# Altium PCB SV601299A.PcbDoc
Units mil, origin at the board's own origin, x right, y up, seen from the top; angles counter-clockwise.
Board outline 3580 x 5000 mil, 2 copper layers (Top Layer, Bottom Layer), stack 62 mil thick; 30 components, 7 nets, 89 pads, 15 vias.
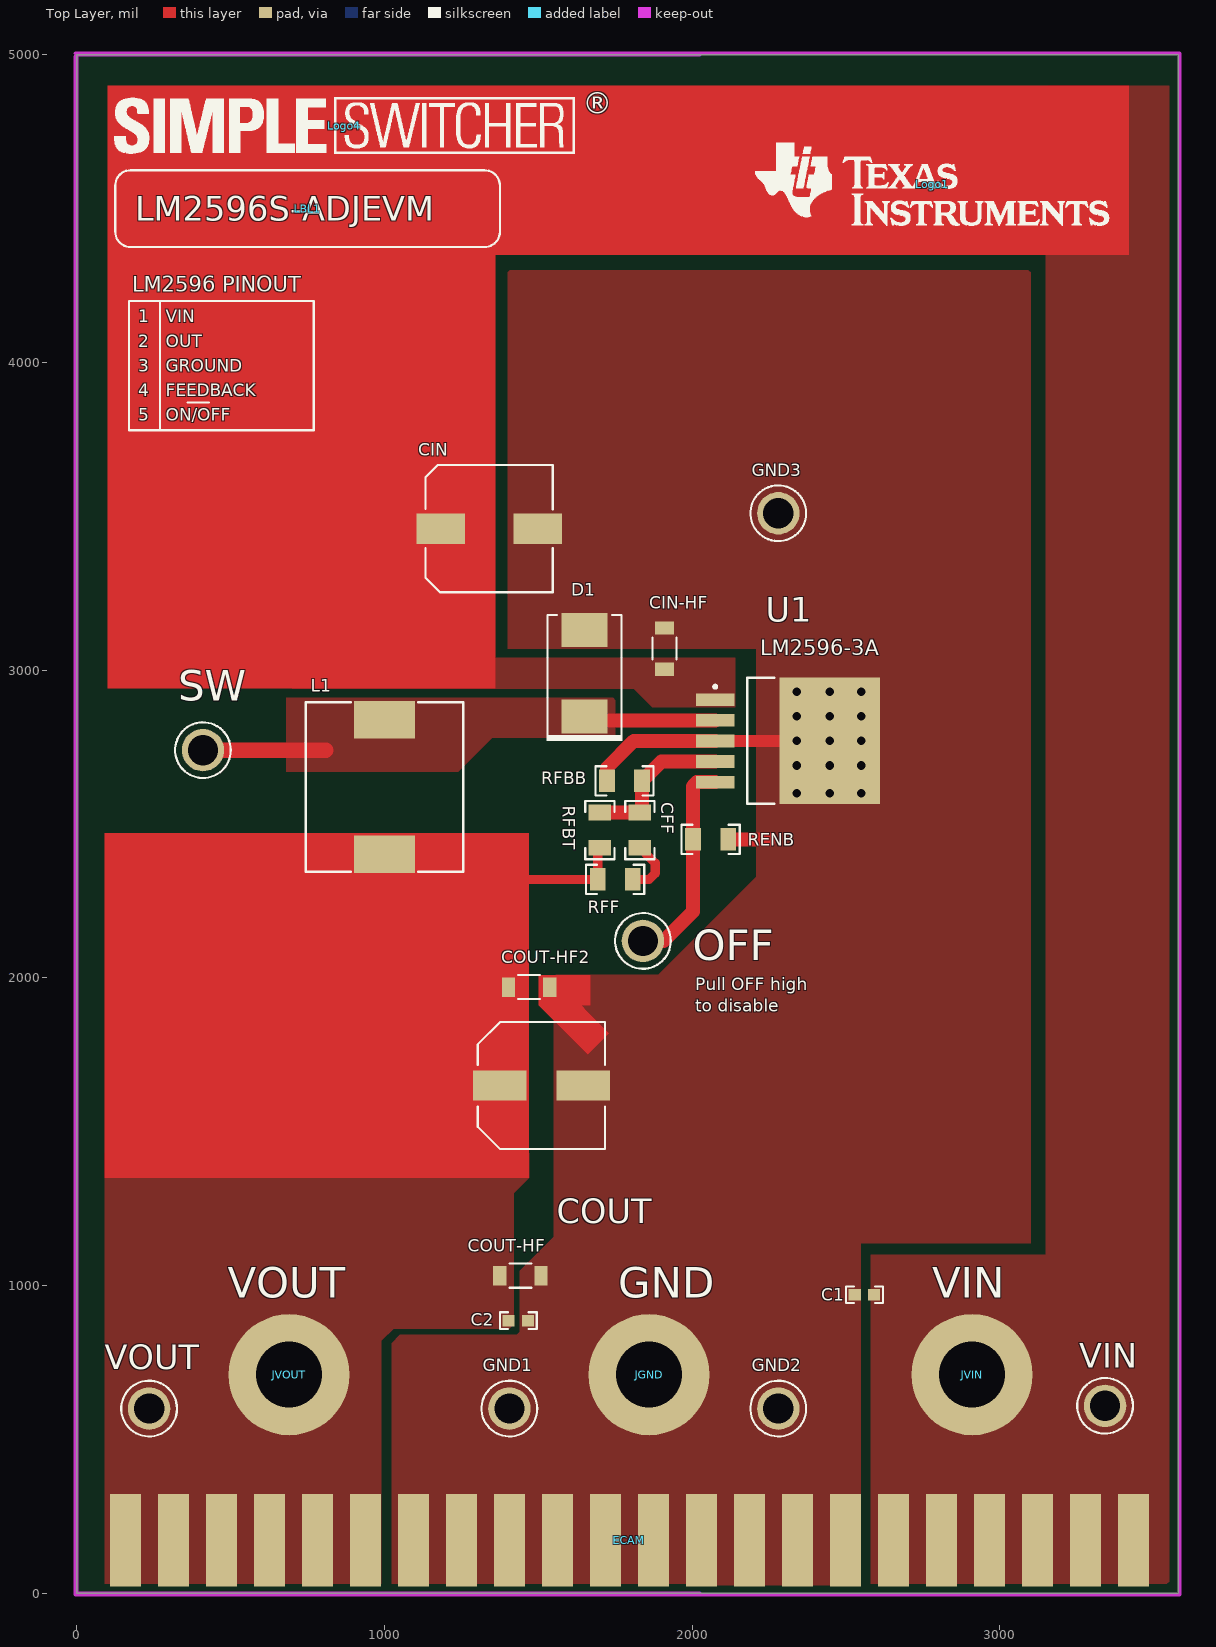
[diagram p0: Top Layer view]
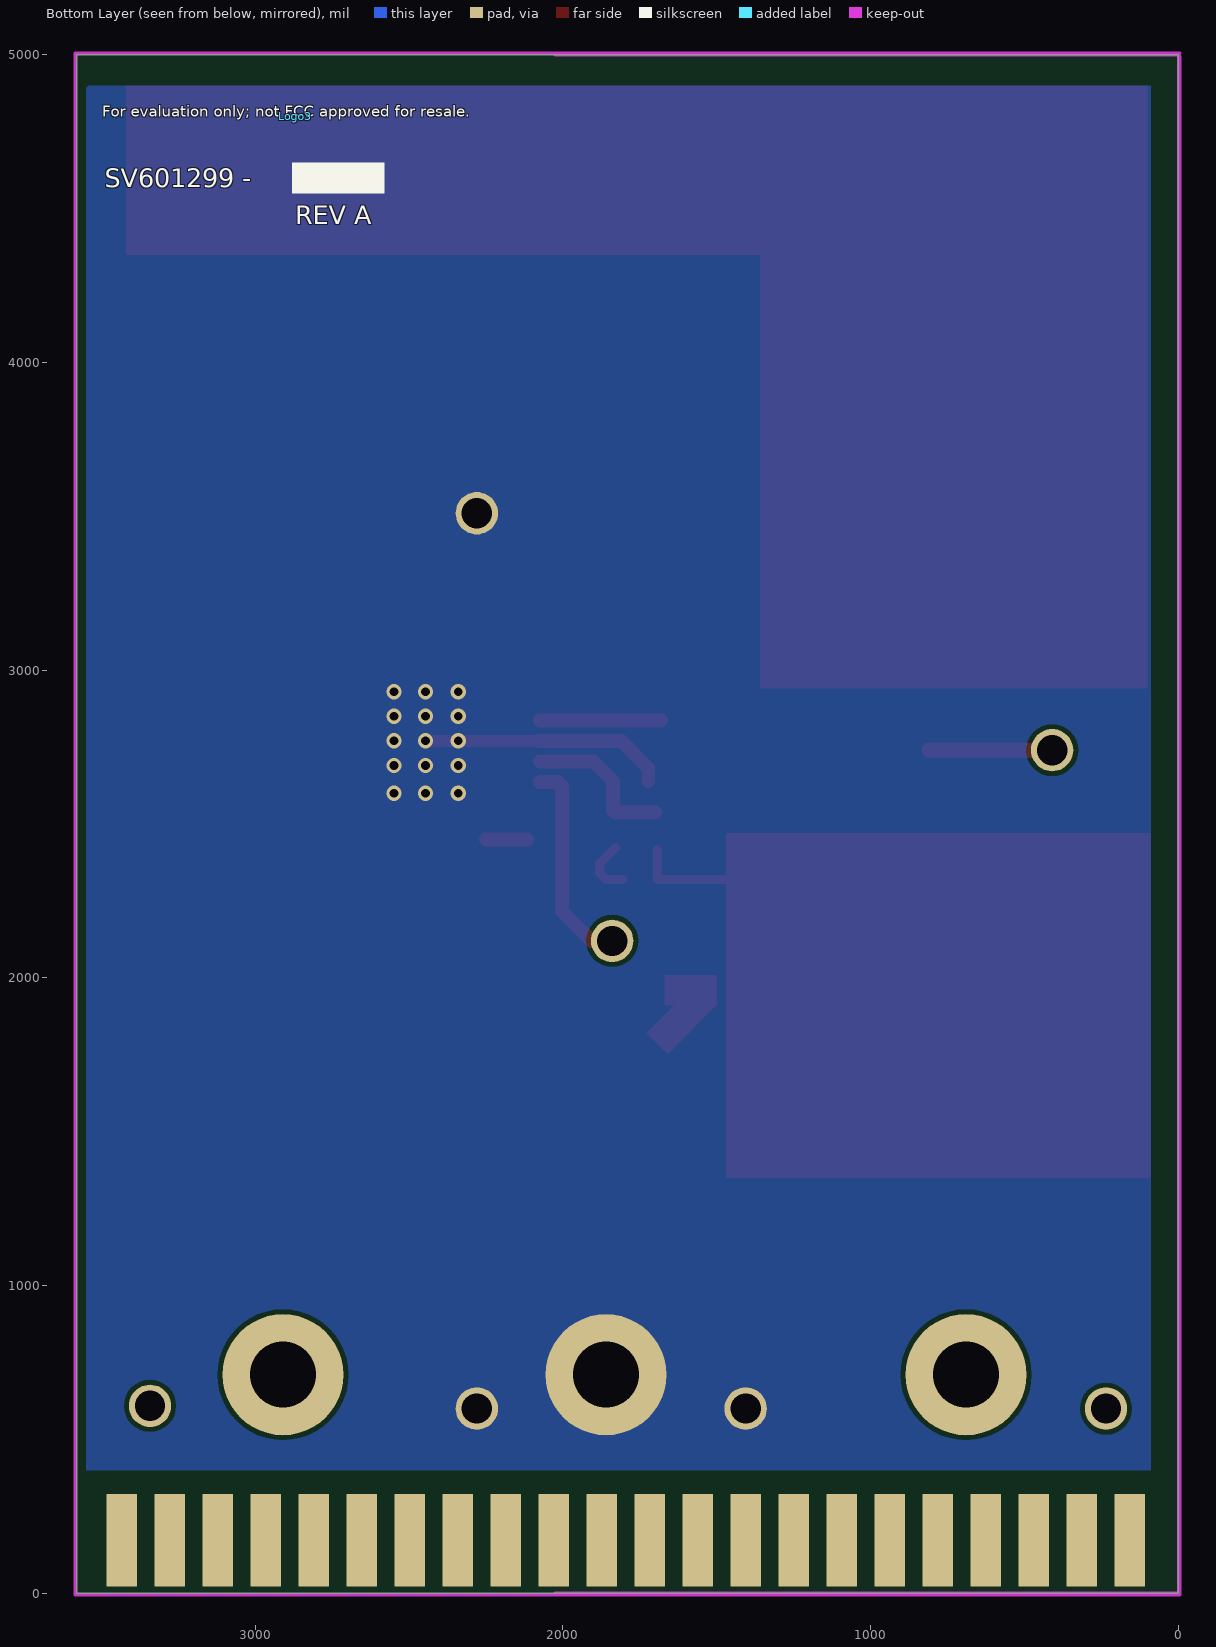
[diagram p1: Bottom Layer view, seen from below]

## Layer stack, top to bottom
Top Solder: solder mask 0.4, Solder Resist, Dk 3.5
Top Layer: signal copper 1.4
Dielectric1: core 59.2, FR-4, Dk 4.8
Bottom Layer: signal copper 1.4
Bottom Solder: solder mask 0.4, Solder Resist, Dk 3.5

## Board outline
0,0 0,5000 3580,5000 3580,0

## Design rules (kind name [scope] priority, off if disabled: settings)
AcuteAngle [All] p1: minimum=4.50000000000000E+0001 checktracksonly=FALSE
AssemblyTestPointUsage [All] p1: valid=2
Clearance Clearance_Keepouts [((IsTrack Or IsArc) And Not InPoly) And IsFree and IsKeepOut vs ((IsTrack Or IsArc) And Not InPoly) And IsFree and IsKeepOut] p1: gap=0
Clearance Clearance_BoardEdge_MountingHoles [OnCopper and InComponentClass('Mounting Holes') vs IsKeepOut] p2: gap=40
Clearance Clearance_BoardEdge_Poly [OnCopper and InPoly vs IsKeepOut] p3: gap=25
Clearance Clearance_BoardEdge [OnCopper and Not InComponentClass('Logo') and not InComponentClass('FiducialMark') and not InRegion(1000,500,4000,800) and Not IsKeepout vs IsKeepOut] p4: gap=15
Clearance Clearance_Poly [InPolygon] p5: gap=15
Clearance [All] p6: gap=7.87
ComponentClearance ComponentClearance_MountingHoles_FiducialMarks [InComponentClass('Mounting Holes') vs InComponentClass('FiducialMark')] p1: gap=50 collisioncheckmode=3 verticalgap=10 showdistances=FALSE
ComponentClearance ComponentClearance_Shunt [InComponentClass('Header') vs InComponentClass('Shunt')] p2: gap=0 collisioncheckmode=3 verticalgap=0 showdistances=FALSE
ComponentClearance ComponentClearance_Logo [InComponentClass('Logo')] p3: gap=50 collisioncheckmode=3 verticalgap=10 showdistances=FALSE
ComponentClearance ComponentClearance_ScrewToNut [(HasFootprint('NY PMS 440 0025 PH')) vs (HasFootprint('Keystone_1902C'))] p4: gap=5 collisioncheckmode=3 verticalgap=10 showdistances=FALSE
ComponentClearance ComponentClearance_MountingHoles [InComponentClass('Mounting Holes')] p5: gap=250 collisioncheckmode=3 verticalgap=100000 showdistances=FALSE
ComponentClearance ComponentClearance_SmallPassives [HasFootprint('0201*') or HasFootprint('0402*') or HasFootprint('0508') or HasFootprint('0603*') or HasFootprint('0612') or HasFootprint('0805*') or HasFootprint('0815*') or HasFootprint('0830*') or HasFootprint('1206*') or HasFootprint('1210*') or HasFootprint('1808*') or HasFootprint('1812*') or HasFootprint('1825*') or HasFootprint('2010*') or HasFootprint('2220*') or HasFootprint('2225*') or HasFootprint('2512*') or HasFootprint('2728*') or HasFootprint('3518*') vs HasFootprint('0201*') or HasFootprint('0402*') or HasFootprint('0508') or HasFootprint('0603*') or HasFootprint('0612') or HasFootprint('0805*') or HasFootprint('0815*') or HasFootprint('0830*') or HasFootprint('1206*') or HasFootprint('1210*') or HasFootprint('1808*') or HasFootprint('1812*') or HasFootprint('1825*') or HasFootprint('2010*') or HasFootprint('2220*') or HasFootprint('2225*') or HasFootprint('2512*') or HasFootprint('2728*') or HasFootprint('3518*')] p6: gap=20 collisioncheckmode=3 verticalgap=10 showdistances=FALSE
ComponentClearance ComponentClearance_THtoSMT [IsThruComponent vs IsSMTComponent] p7: gap=100 collisioncheckmode=3 verticalgap=30 showdistances=FALSE
ComponentClearance ComponentClearance_THtoTH [IsThruComponent vs IsThruComponent] p8: gap=118.11 collisioncheckmode=3 verticalgap=30 showdistances=FALSE
ComponentClearance [All] p9: gap=40 collisioncheckmode=3 verticalgap=10 showdistances=FALSE
DiffPairsRouting [All] p1: maxlimit=100 minlimit=10 mostfreqgap=10 toplayer_minwidth=15 toplayer_maxwidth=15 toplayer_prefwidth=15 bottomlayer_minwidth=15 bottomlayer_maxwidth=15 bottomlayer_prefwidth=15 maxuncoupledlength=1000
FabricationTestPointUsage TestPointUsage [All] p1: valid=2 allowmultiple=FALSE
FabricationTestpoint Testpoint [All] p1: side=3 testpointundercomponent=TRUE minsize=40 maxsize=100 preferedsize=60 minholesize=0 maxholesize=40 preferedholesize=32 testpointgrid=1 allowsidetop=TRUE allowsidebottom=TRUE usegrid=TRUE gridtolerance=0.01
FanoutControl Fanout_LCC [IsLCC] p1: bgadir=Out bgaviamode=Centered fanoutstyle=Auto fanoutdirection=Alternating viagrid=1 // Fanout_LCC (Default Rule)
FanoutControl Fanout_BGA [IsBGA] p2: bgadir=Out bgaviamode=Centered fanoutstyle=Auto fanoutdirection=Alternating viagrid=1 // Fanout_BGA (Default Rule)
FanoutControl Fanout_Default [All] p4: bgadir=Out bgaviamode=Centered fanoutstyle=Auto fanoutdirection=Alternating viagrid=1 // Fanout_Default (Default Rule)
FanoutControl Fanout_Small [(CompPinCount < 5)] p5: bgadir=Out bgaviamode=Centered fanoutstyle=Auto fanoutdirection=OutThenIn viagrid=1 // Fanout_Small (Default Rule)
HoleSize [All] p1: absolutevalues=TRUE maxlimit=251 minlimit=8 maxpercent=80.000 minpercent=20.000
MinimumAnnularRing MinimumAnnularRing_ThermalPadVias [IsVia and InAnyComponent] p1: minimumring=5.91
MinimumAnnularRing [All] p2: minimumring=6
MinimumSolderMaskSliver MinimumSolderMaskSliver_Logo [InComponentClass('Logo') vs InComponentClass('Logo')] p1: minsoldermaskwidth=0.7
MinimumSolderMaskSliver [All] p2: minsoldermaskwidth=3
PlaneConnect [All] p1: planeconnectstyle=Relief reliefexpansion=10 reliefentries=4 reliefconductorwidth=10 reliefairgap=10
PolygonConnect [All] p1: connectstyle=Direct reliefconductorwidth=10 reliefentries=4 polygonreliefangle="90 Angle" airgapwidth=10
RoutingVias ThermalPadVias [IsVia and InAnyComponent] p1: holewidth=7.87 width=19.68 viastyle="Through Hole" minholewidth=7.87 minwidth=19.68 maxholewidth=12.99 maxwidth=23.62
RoutingVias [All] p2: holewidth=16 width=34 viastyle="Through Hole" minholewidth=7.87 minwidth=24 maxholewidth=40 maxwidth=65
SilkToBoardRegionClearance [Not ((IsComment or IsDesignator) And (Hide <> 'False')) and not InRegion(1000,500,4000,800)] p1:
SilkToSilkClearance SilkToSilkClearance_Pb-FreeLogo [(HasFootprint('Pb-Free_Overlay_Medium') OR HasFootprint('Pb-Free_Overlay_Small')) vs (HasFootprint('Pb-Free_Overlay_Medium') OR HasFootprint('Pb-Free_Overlay_Small'))] p1: silktosilkclearance=0
SilkToSilkClearance [All] p2: silktosilkclearance=4
SilkToSolderMaskClearance "Silk to Solder Mask Opening" [All] p1: minsilkscreentomaskgap=3 clearancetoexposedcopper=FALSE
SolderMaskExpansion [All] p1: expansion=1.97
Width [All] p1: maxlimit=100 minlimit=6 preferedwidth=10 checkconnectedcopper=TRUE
15 further rules are at their usual default settings.

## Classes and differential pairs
component class Label: LBL1
component class Logo: Logo1 Logo4

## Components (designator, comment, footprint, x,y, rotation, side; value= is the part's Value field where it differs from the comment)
C1 "C1608X7R2A223K080AA" 0603 2560,970 r180 top
C2 "C1608X7R1C224K080AC" 0603 1435,886 r0 top
CFF "12065C332KAT2A" 1206 1830,2480 r270 top
CIN "EEHZC1H101P" SM_RADIAL_10BMM 1340,3460 r0 top
CIN-HF "C3216X7R2A474K160AA" 1206_180 1910,3070 r90 top
COUT "EEE-FP1V331AP" CAPAE1030X1080 1510,1650 r0 top
COUT-HF "C3216X7R2A474K160AA" 1206_180 1442,1032 r0 top
COUT-HF2 "C3216X7R2A474K160AA" 1206_180 1470,1970 r0 top
D1 "B550C-13-F" SMC 1650,2990 r90 top
ECAM "PCB Edge Pattern Feature" "EDAC 2X22_am" 1796,172 r0 top
GND1 "Suggest using a net name here" Keystone1502-2 1406,600 r0 top locked
GND2 "Suggest using a net name here" Keystone1502-2 2280,600 r270 top
GND3 "Suggest using a net name here" Keystone1502-2 2280,3510 r0 top
JGND "575-8" Keystone575-8 1860,710 r90 top
JVIN "575-8" Keystone575-8 2910,710 r90 top
JVOUT "575-8" Keystone575-8 690,710 r90 top
L1 "SRP1265A-470M" SRP1265A 1000,2620 r270 top
LBL1 "Size: 1.25\" x 0.25\"" Label_1250x250 750,4500 r0 top
Logo1 "Texas Instruments" TI_Stacked_Overlay_Medium 2780,4580 r0 top
Logo3 "FCC disclaimer" FCC_disclaimer 2870,4800 r180 bottom
Logo4 "Simple Switcher" SS_Overlay_Medium 870,4770 r0 top
OFF "Suggest using a net name here" Keystone1502-2 1840,2120 r270 top
RENB "CRCW12061K02FKEA" 1206 2060,2450 r180 top
RFBB "ERJ-8ENF1001V" 1206 1780,2640 r0 top
RFBT "CRCW12063K09FKEA" 1206 1700,2480 r270 top
RFF "CRCW1206100RJNEA" 1206 1750,2320 r0 top
SW "Suggest using a net name here" Keystone1502-2 410,2740 r90 top
U1 "LM2596S-ADJ/NOPB" TS5B_N 2311,2770 r0 top
VIN "Suggest using a net name here" Keystone1502-2 3342,609 r0 top
VOUT "Suggest using a net name here" Keystone1502-2 235,600 r0 top locked

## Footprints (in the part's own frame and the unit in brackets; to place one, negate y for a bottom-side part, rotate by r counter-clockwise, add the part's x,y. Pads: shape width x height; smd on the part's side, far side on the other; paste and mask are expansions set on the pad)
0603 [mm] "0603 from SM-752 data"
  rect 1x0.95 smd: 1(-0.8,0) 2(0.8,0)
  silkscreen extent -1.52,-0.69 1.52,0.69, body extent -0.87,-0.47 0.87,0.47, height 1
1206 [mm] "1206 from SM-752 data"
  rect 1.3x1.85 smd: 1(-1.45,0) 2(1.45,0)
  silkscreen extent -2.4,-1.21 2.4,1.21, body extent -1.7,-0.9 1.7,0.9, height 1.35
1206_180 [mm] "1206_180"
  rect 1.1x1.6 smd: 1(-1.7,0) 2(1.7,0)
  silkscreen extent -0.9,-1 0.9,1, body extent -1.75,-0.95 1.75,0.95, height 1.8
CAPAE1030X1080 [mm] "10.3 x 10.3 mm base"
  rect 4.4x2.5 smd: 1(-3.45,0) 2(3.45,0)
  silkscreen extent -5.25,-5.25 5.25,5.25, body extent -5.25,-5.25 5.25,5.25, height 10.5
"EDAC 2X22_am" [mil]
  rect 100x300 smd far side: 1(1638,0) 2(1482,0) 3(1326,0) 4(1170,0) 5(1014,0) 6(858,0) 7(702,0) 8(546,0) 9(390,0) 10(234,0) 11(78,0) 12(-78,0) 13(-234,0) 14(-390,0) 15(-546,0) 16(-702,0) 17(-858,0) 18(-1014,0) 19(-1170,0) 20(-1326,0) 21(-1482,0) 22(-1638,0)
  rect 100x300 smd: A(1638,0) B(1482,0) C(1326,0) D(1170,0) E(1014,0) F(858,0) H(702,0) J(546,0) K(390,0) L(234,0) M(78,0) N(-78,0) P(-234,0) R(-390,0) S(-546,0) T(-702,0) U(-858,0) V(-1014,0) W(-1170,0) X(-1326,0) Y(-1482,0) Z(-1638,0)
FCC_disclaimer [mil]
Keystone575-8 [mm] "Banana Jack"
  round 10 hole 5.45: 1(0,0)
  body extent -3.92,-3.94 3.95,3.94, height 2.36
Keystone1502-2 [mm] "Double Turret"
  round 3.5 hole 2.5: 1(0,0)
  silkscreen extent -2.3,-2.3 2.3,2.3, body extent -1.6,-1.6 1.59,1.6, height 5.62
Label_1250x250 [mil] "Thermal Transfer Labels"
  round 1 on Mech13: 0(0,0)
  silkscreen extent -625,-125 625,125, body extent -625,-125 625,125, height 1
SM_RADIAL_10BMM [mm] "Nichicon 10x10"
  rect 4x2.5 smd: 1(-4,0) 2(4,0)
  silkscreen extent -5.25,-5.25 5.25,5.25, body extent -5.25,-5.25 5.25,5.25, height 10.5
SMC [mil] "Molded Diode, 2-Leads, Body 6.9x5.8mm, IPC Medium Density, based on OnSemi component dimensions and land patterns"
  rect 110x150 smd: 1(-140.49,0) 2(140.49,0)
  silkscreen extent -221,-124 189,123, body extent -156,-116 156,116, height 91
SRP1265A [mm] "BOURNS"
  rect 3.1x5 smd: 1(-5.55,0) 2(5.55,0)
  silkscreen extent -7,-6.5 7,6.5, body extent -6.95,-6.4 6.95,6.4, height 6.4
SS_Overlay_Medium [mil]
  silkscreen extent -748,-91 749,92
TI_Stacked_Overlay_Medium [mil]
  silkscreen extent -576,-136 576,134
TS5B_N [mm] "D2-PAK, 6-Leads, Body 8.6x10.2mm, Pitch 1.7mm, Lead Span 14.1mm, IPC Medium Density"
  rect 3.2x1.05 smd: 1(-6,3.4) 2(-6,1.7) 3(-6,0) 4(-6,-1.7) 5(-6,-3.4)
  rect 8.3x10.45 smd: 6(3.45,0)
  silkscreen extent -6.12,-5.2 -1.1,5.2, body extent -3.35,-5.2 6.05,5.2, height 4.65

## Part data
C1: "CAP, CERM, 0.022 µF, 100 V, +/- 10%, X7R, 0603"
C2: "CAP, CERM, 0.22 µF, 16 V, +/- 10%, X7R, 0603"
CFF: "CAP, CERM, 3300 pF, 50 V, +/- 10%, X7R, 1206"
CIN: "CAP, Polymer Hybrid, 100 µF, 50 V, +/- 20%, 28 ohm, 10x10 SMD"
CIN-HF COUT-HF COUT-HF2: "CAP, CERM, 0.47 µF, 100 V, +/- 10%, X7R, 1206"
COUT: "CAP, AL, 330 µF, 35 V, +/- 20%, 0.06 ohm, SMD"
D1: "Diode, Schottky, 50 V, 5 A, SMC"
ECAM: library part "EDAC 2x22_AM", "EDAC Edge 2x22 Contact Edge Connector Feature"
GND1 GND2 GND3 OFF SW VIN VOUT: library part 1502-2, "Terminal, Turret, TH, Double"
JGND JVIN JVOUT: "Standard Banana Jack, Uninsulated, 8.9mm"
L1: "Inductor, Shielded, 47 µH, 6.5 A, 0.076 ohm, AEC-Q200 Grade 0, SMD"
LBL1: library part THT-13-457-10, "Thermal Transfer Printable Labels, 1.250\" W x 0.250\" H - 10,000 per roll"
Logo1: library part TI_Logo, "Texas Instrument Corporate Signature"
Logo3: library part FCC_disclaimer, "FCC_disclaimer"
Logo4: library part SimpleSwitcher, "Simple Switcher Logo"
RENB: "RES, 1.02 k, 1%, 0.25 W, 1206"
RFBB: "RES, 1.00 k, 1%, 0.25 W, 1206"
RFBT: "RES, 3.09 k, 1%, 0.25 W, 1206"
RFF: "RES, 100, 5%, 0.25 W, 1206"
U1: "SIMPLE SWITCHER® Power Converter 150 KHz 3A Step-Down Voltage Regulator, 5-pin TO-263, Pb-Free"

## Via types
v1: diameter 50, hole 28, Top Layer to Bottom Layer, 15 vias

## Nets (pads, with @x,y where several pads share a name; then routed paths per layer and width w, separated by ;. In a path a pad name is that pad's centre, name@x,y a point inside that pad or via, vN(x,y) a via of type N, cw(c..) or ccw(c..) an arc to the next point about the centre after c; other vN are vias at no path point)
EN: OFF.1 RENB.2 U1.5 | length 687
  Top Layer w45: OFF.1 1907.09,2120 2002.91,2215.83 RENB.2 2002.91,2622.91 2016.14,2636.14 U1.5
FB: CFF.1 RFBB.2 RFBT.1 U1.4 | length 499.7
  Top Layer w45: RFBT.1 CFF.1 1837.09,2544.17 RFBB.2 1900.16,2703.07 U1.4
GND: C1.2 C2.2 CIN-HF.2 CIN.2 COUT-HF2.2 COUT-HF.2 COUT.2 D1.2 ECAM.H ECAM.J ECAM.K ECAM.L ECAM.M ECAM.N ECAM.P ECAM.R ECAM.S ECAM.T GND1.1 GND2.1 GND3.1 JGND.1 RENB.1 RFBB.1 U1.3 U1.6 | length 935.8
  Top Layer w40: U1.3 v1(2446.83,2770)
  Top Layer w45: RFBB.1 1722.91,2682.91 1810,2770 U1.3 ; RENB.1 2250,2450
  other v1: 2340,2600 2446.83,2600 2549.19,2600 2340,2690 2446.83,2690 2549.19,2690 2340,2770 2549.19,2770 2340,2850 2446.83,2850 2549.19,2850 2340,2930 2446.83,2930 2549.19,2930
NetCFF_2: CFF.2 RFF.2 | length 184.8
  Top Layer w30: RFF.2 1860,2320 1880,2340 1880,2372.91 CFF.2
SW: D1.1 L1.1 SW.1 U1.2 | length 810.7
  Top Layer w10: D1.1@1676,2841.51 D1.1@1680.58,2836.93
  Top Layer w45: D1.1@1680.58,2836.93 U1.2
  Top Layer w50: SW.1@400,2740 810,2740
VIN: C1.1 CIN-HF.1 CIN.1 ECAM.A ECAM.B ECAM.C ECAM.D ECAM.E ECAM.F JVIN.1 U1.1 VIN.1
VOUT: C2.1 COUT-HF2.1 COUT-HF.1 COUT.1 ECAM.U ECAM.V ECAM.W ECAM.X ECAM.Y ECAM.Z JVOUT.1 L1.2 RFBT.2 RFF.1 VOUT.1 | length 618.7
  Top Layer w30: 1360,2320 RFF.1 RFBT.2@1692.91,2415.83 ; COUT-HF2.1@1412.91,1960 1412.91,2150
pads on no net: ECAM.1 ECAM.2 ECAM.3 ECAM.4 ECAM.5 ECAM.6 ECAM.7 ECAM.8 ECAM.9 ECAM.10 ECAM.11 ECAM.12 ECAM.13 ECAM.14 ECAM.15 ECAM.16 ECAM.17 ECAM.18 ECAM.19 ECAM.20 ECAM.21 ECAM.22 LBL1.0

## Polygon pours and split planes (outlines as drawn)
GND on Top Layer "GND_L01_P002" (solid, remove dead copper, pour order 2): 2548,1137 3100,1137 3100,4300 2208,4300 2208,3283 2208,2328 1890,2010 1550,2010 1550,1158 1440,1048 1440,850 1430,840 1050,840 1023,813 1023,24 2548,24
VIN on Top Layer "Top Layer-No Net" (solid, remove dead copper, pour order 5): 2140,2880 1870,2880 1810,2940 700,2940 700,3040 1830,3040 2140,3040
GND on Top Layer "Top Layer-No Net 1" (solid, remove dead copper, pour order 7): 2280,3070 1400,3070 1400,4300 2280,4300
SW on Top Layer "Top Layer-No Net 2" (solid, remove dead copper, pour order 9): 1750,2910 680,2910 680,2670 1240,2670 1350,2780 1750,2780
VIN on Top Layer "Top Layer-No Net 3" (solid, remove dead copper, pour order 11): 3550,30 2580,30 2580,1100 3150,1100 3150,4900 3550,4900
VOUT on Top Layer "Top Layer-No Net 4" (solid, remove dead copper, pour order 13): 110,30 990,30 990,820 1030,860 1406.05,860 1420,873.95 1420,1300 1470,1350 1470,1430 90,1430 90,30
GND on Bottom Layer "Bottom Layer-No Net" (solid, remove dead copper, pour order 15): 3550,400 90,400 90,4900 3542.93,4900 3550,4892.93

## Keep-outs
Keep-Out Layer:
  lines w10: -5,-5 3585,-5 3585,5005 -5,5005 ; -5,-4 -5,4996 ; 2026,0 0,0 0,5000 2026,5000
  text ".Layer_Name" at 577,-858.49 h60

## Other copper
Top Layer:
  rectangle net VIN: 100,4350 3420,4900
  rectangle net VIN: 100,2940 1360,4520
  rectangle net VOUT: 90,1350 1470,2470
  rectangle net GND: 1500,1910 1670,2010
  region net GND: 1730.71,1820.71 1570.5,1980.92 1499.79,1910.21 1660,1750
  text ".Layer_Name" at 577,-858.49 h60
Bottom Layer:
  text ".Layer_Name" at 577,-858.49 h60

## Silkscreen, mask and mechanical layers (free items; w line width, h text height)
Top Overlay:
  lines w7: 270,3780 270,4200 ; 360,3870 430,3870 ; 170,3780 170,4200 770,4200 770,3780 170,3780
  text "LM2596S-ADJEVM" at 190,4460 h80
  text "LM2596 PINOUT" at 180,4230 h50
  text "1   VIN" at 200,4130 h40
  text "2   OUT" at 200,4050 h40
  text "3   GROUND" at 200,3970 h40
  text "4   FEEDBACK" at 200,3890 h40
  text "5   ON/OFF" at 200,3810 h40
  text "LM2596-3A" at 2221,3049 h50
  text "Pull OFF high" at 2010,1960 h40
  text "to disable" at 2010,1890 h40
  text "VOUT" at 490,960 h100
  text "GND" at 1760,960 h100
  text "VIN" at 2780,960 h100
  text ".Layer_Name" at 577,-858.49 h60
Bottom Overlay:
  rectangle: 2580,4550 2880,4650
  text "SV601299 -" at 3490,4570 h60
  text "REV A" at 2870,4450 h60
  text ".Layer_Name" at 577,-858.49 h60
Top Paste:
  text ".Layer_Name" at 577,-858.49 h60
Bottom Paste:
  text ".Layer_Name" at 577,-858.49 h60
Top Solder:
  rectangle: 0,0 3580,330
  text ".Layer_Name" at 577,-858.49 h60
  text ".Layer_Name" at 577,-858.49 h60
Bottom Solder:
  text ".Layer_Name" at 577,-858.49 h60
Drill Guide:
  text ".Layer_Name" at 577,-858.49 h60
M1 Board Outline:
  lines w10: 316,-1 319,-4 ; 321,3 324,0 ; 0,0 0,5000 3580,5000 3580,0 0,0
  text ".Layer_Name" at 577,-858.49 h60
M2 Board Dimensions:
  rectangle: 125,-400 500,-275
  rectangle: 0,-275 125,-150
  lines w7: 0,-275 1000,-275 ; 125,-400 125,-150 ; 250,-400 250,-150 ; 500,-400 500,-150 ; 750,-400 750,-150 ; 0,-400 0,-150 1000,-150 1000,-400 0,-400
  text ".Layer_Name" at 577,-858.49 h60
M3 3D STEP Top:
  text ".Layer_Name" at 577,-858.49 h60
M4 3D STEP Bottom:
  text ".Layer_Name" at 577,-858.49 h60
M5 Assembly Top:
  lines w10: -292,-930.17 6308,-930.17 ; -292,-726.83 6310,-726.83 ; -292,-523.5 -292,-1133.5 3713,-1133.5 6310,-1133.5 6310,-523.5 -291.5,-523.5 -291.5,-1133.5 1284,-1133.5 ; 2173,-1133.5 2173,-523.5 ; 3440,-726.83 3440,-523.5 ; 4280,-726.83 4280,-523.5 ; 4902,-1140 4902,-937.17
  text "COMPONENTS MARKED 'DNP' SHOULD NOT BE POPULATED." at 1153.5,-318.5 h60
  text "ASSEMBLY VARIANT:" at 1153,-434 h60
  text ".VariantName" at 2189,-434 h60
  text "PCB VIEWED FROM TOP SIDE" at -228.5,-655.67 h60
  text "BOARD #:" at 2248,-655.67 h60
  text ".PRJ_Number" at 2793.5,-655.67 h60
  text "REV:" at 3638,-655.67 h60
  text ".PCB_Rev" at 3929.5,-655.67 h60
  text "SVN REV:" at 4476,-655.67 h60
  text ".VersionControl_RevNumber" at 4982,-655.67 h60
  text "TID #:" at 2248,-859 h60
  text ".TID" at 2793.5,-859 h60
  text "PLOT NAME =" at -228.5,-1064.34 h60
  text ".plot_File_Name" at 577,-1064.34 h60
  text "GENERATED    :" at 2250,-1064.34 h60
  text ".Print_Date" at 3119.5,-1064.34 h60
  text ".Print_Time" at 3848.5,-1064.34 h60
  text "TEXAS INSTRUMENTS" at 5113,-1064.34 h60
M6 Assembly Bottom:
  lines w10: -292.5,-727.33 6309.5,-727.33 ; -290.5,-930.67 6309.5,-930.67 ; 1115.5,-1140.5 1115.5,-937.67 ; 1737.5,-727.33 1737.5,-524 ; 2577.5,-727.33 2577.5,-524 ; 3844.5,-1134 3844.5,-524 ; 4733.5,-1134 6309,-1134 6309,-524 -292.5,-524 -292.5,-1134 2304.5,-1134 6309.5,-1134 6309.5,-524
  text "COMPONENTS MARKED 'DNP' SHOULD NOT BE POPULATED." at 6102,-318 h60
  text ".VariantName" at 5058,-434 h60
  text "ASSEMBLY VARIANT:" at 6097,-434 h60
  text ".VersionControl_RevNumber" at 1035.5,-656.17 h60
  text "SVN REV:" at 1541.5,-656.17 h60
  text ".PCB_Rev" at 2088,-656.17 h60
  text "REV:" at 2379.5,-656.17 h60
  text ".PRJ_Number" at 3224,-656.17 h60
  text "BOARD #:" at 3769.5,-656.17 h60
  text "PCB VIEWED FROM BOTTOM SIDE" at 6246,-656.17 h60
  text ".TID" at 3224,-859.5 h60
  text "TID #:" at 3769.5,-859.5 h60
  text "TEXAS INSTRUMENTS" at 904.5,-1064.84 h60
  text ".Print_Time" at 2169,-1064.84 h60
  text ".Print_Date" at 2898,-1064.84 h60
  text "GENERATED    :" at 3767.5,-1064.84 h60
  text ".plot_File_Name" at 5440.5,-1064.84 h60
  text "PLOT NAME =" at 6246,-1064.84 h60
M9 Title Sheet:
  drawing of 57 lines, arcs and shapes, not listed
  text "1" at 739.84,8036.5 h70
  text "2" at 3235.5,8036.5 h70
  text "3" at 5724.84,8036.5 h70
  text "4" at 8231.51,8036.5 h70
  text "5" at 10730.5,8036.5 h70
  text "6" at 13235.5,8036.5 h70
  text "A" at -416.5,6893.5 h70
  text "A" at 14383.5,6893.5 h70
  text "B" at -416.5,4513.5 h70
  text "B" at 14383.5,4513.5 h70
  text "C" at -416.5,2138.5 h70
  text "C" at 14383.5,2138.5 h70
  text "PROJECT TITLE:" at 11343.5,277.5 h45
  text ".PRJ_Title" at 11393.5,144.17 h70
  text "DESIGNED FOR:" at 11343.5,-23.5 h45
  text ".PRJ_Customer" at 11393.5,-163.5 h70
  text "D" at -416.5,-231.5 h70
  text "D" at 14383.5,-231.5 h70
  text "FILE NAME:" at 11343.5,-323.5 h45
  text ".PCB_File_Name_No_Path" at 11393.5,-443.5 h70
  text "Texas Instruments (TI) and/or its licensors do not warrant the accuracy or completeness of this specification" at 6374,-605.34 h45
  text "ENGINEER:" at 11343.5,-613.5 h45
  text "LAYOUT BY:" at 12848.5,-613.5 h45
  text "or any information contained therein. TI and/or its licensors do not warrant that this design will meet" at 6329.01,-718 h45
  text ".PRJ_Engineer" at 11393.5,-768.49 h70
  text ".PCB_Layout" at 12899,-768.49 h70
  text "the specifications, will be suitable for your application or fit for any particular purpose, or will operate in" at 6329.01,-830.67 h45
  text ".Layer_Name" at 577,-858.49 h60
  text "ALTIUM DESIGNER VERSION:" at 12848.5,-923.5 h45
  text "an implementation. TI and/or its licensors do not warrant that the design is production worthy. You should" at 6329.01,-943.33 h45
  text "completely validate and test your design implementation to confirm the system functionality for your application." at 6374,-1056 h45
  text ".print_Scale" at 11393.5,-1056.83 h70
  text ".Application_BuildNumber" at 12899,-1056.83 h70
  text "1" at 739.84,-1263.5 h70
  text "2" at 3235.5,-1263.5 h70
  text "3" at 5724.84,-1263.5 h70
  text "4" at 8231.51,-1263.5 h70
  text "5" at 10730.5,-1263.5 h70
  text "6" at 13235.5,-1263.5 h70
M10 Fab Notes:
  drawing of 185 lines, arcs and shapes, not listed
  text "DESIGN INFORMATION" at 12381.02,5910 h60
  text "MIN. TRACK WIDTH:" at 11736.46,5730 h60
  text "8" at 12832.7,5730 h60
  text "MIL" at 12987.46,5730 h60
  text "MIN. CLEARANCE:" at 11736.46,5598 h60
  text "0.2" at 12772.7,5598 h60
  text "mm" at 12987.46,5598 h60
  text "MIN. VIA PAD SIZE:" at 11736.46,5466 h60
  text "24" at 12802.71,5466 h60
  text "MIL" at 12987.46,5466 h60
  text "0.05mm (2MIL)" at 12431.46,5324.29 h60
  text "MINIMUM ANNULAR RING" at 11407.23,5320 h60
  text "EXTERNAL" at 13139.46,5320 h60
  text "PER" at 11607.23,5202 h60
  text "IPC-D-275 CLASS 2 LEVEL C" at 11827.23,5202 h60
  text "MIL, HOLES" at 13315.46,5089.71 h60
  text "+/-" at 12923,5089 h60
  text "+/-" at 13777,5089 h60
  text "REGISTRATION TOLERANCES:" at 11407.23,5084 h60
  text "METAL" at 12607,5084 h60
  text "5" at 13183.2,5084 h60
  text "3" at 14016.2,5084 h60
  text "MIL" at 14132.46,5084 h60
  text "MATERIAL:" at 11332.46,4874.54 h60
  text "FR-4 High Tg" at 12318.9,4734.21 h60
  text "FR-408" at 11753.46,4725.64 h60
  text "X" at 12165.46,4725.64 h60
  text "OTHER" at 13241.46,4725.64 h60
  text "62 MIL (1.6mm) +/-10%" at 12073.56,4562.92 h60
  text "THICKNESS:" at 11407.23,4558.64 h60
  text "X" at 11945.4,4558.64 h60
  text "OTHER" at 13358.46,4558.64 h60
  text "TOLERANCE:" at 11407.23,4400.64 h60
  text "X" at 12246.53,4400.64 h60
  text "ANSI IPC-6012 TYPE 3 CLASS 2" at 12433.48,4400.64 h60
  text "OTHER +/-" at 12433.46,4244.64 h60
  text "BOW & TWIST:" at 11407.23,4087.64 h60
  text "X" at 12246.53,4087.64 h60
  text "ANSI IPC-6012 TYPE 3 CLASS 2" at 12433.48,4087.64 h60
  text "OTHER +/-" at 12433.46,3929.13 h60
  text "DRILLING:" at 11332.46,3790.64 h60
  text "REFERENCE:" at 11407.23,3673.64 h60
  text "X" at 12055.46,3673.64 h60
  text "AS SHOWN" at 12242.46,3673.64 h60
  text "X" at 12956.46,3673.64 h60
  text "NC_DRILL FILES" at 13093.46,3673.64 h60
  text "PTH MIN COPPER THICKNESS:" at 11407.23,3515.64 h60
  text "X" at 12757.46,3515.64 h60
  text "1MIL" at 12894.46,3515.64 h60
  text "OTHER" at 13391.46,3515.64 h60
  text "BOARD FINISH:" at 11332.46,3356.64 h60
  text "SILKSCREEN:" at 11487.68,3238.64 h60
  text "X" at 12436.46,3238.64 h60
  text "TOP" at 12562.46,3238.64 h60
  text "X" at 12946.46,3238.64 h60
  text "BOTTOM" at 13073.46,3238.64 h60
  text "SILKSCREEN COLOR:" at 11487.68,3071.64 h60
  text "X" at 12435.42,3071.64 h60
  text "WHITE" at 12562.46,3071.64 h60
  text "OTHER" at 13073.46,3071.64 h60
  text "SOLDER RESIST COLOR:" at 11487.68,2901.64 h60
  text "X" at 12050,2760 h60
  text "GREEN" at 12182.46,2742.44 h60
  text "BLUE" at 12773.46,2742.44 h60
  text "OTHER" at 13311.46,2742.44 h60
  text "IMMERSION GOLD (ENIG)" at 12393.46,2553.92 h60
  text "ENEPIG" at 13731,2550.64 h60
  text "SURFACE FINISH:" at 11332.46,2549.64 h60
  text "X" at 12206.51,2549.64 h60
  text "IMM. TIN/SILVER OR EQUIV" at 11662,2392.64 h60
  text "OTHER" at 13093.46,2392.64 h60
  text "ARRAY/PANEL:" at 11332.46,2213.64 h60
  text "CUT AND TRIM PER MECH LAYER 1" at 12393.46,2209.35 h60
  text "N.C. ROUTE" at 12393.46,2057.64 h60
  text "X" at 13072.46,2057.64 h60
  text "V. SCORE" at 13259.46,2057.64 h60
  text "CERTIFICATION:" at 11332.46,1920.64 h60
  text "MATERIALS AND WORKMANSHIP FOR ALL PCBS" at 12057.46,1920.64 h60
  text "TO MEET OR EXCEED THE REQUIREMENTS OF:" at 12057.46,1822.64 h60
  text "X" at 11683.96,1686.13 h60
  text "ANSI IPC-A-600F CLASS ->" at 11822.96,1686.13 h60
  text "X" at 13462.02,1686.13 h60
  text "2" at 13580.96,1686.14 h60
  text "1" at 13265.96,1684.64 h60
  text "3" at 13934.96,1684.64 h60
  text "X" at 11686.02,1526.64 h60
  text "UL 94V-0" at 11822.96,1526.64 h60
  text "X" at 12498.02,1526.64 h60
  text "RoHS" at 12634.96,1526.64 h60
  text "OTHER" at 13279.36,1526.64 h60
  text "PER ORDER" at 13676.42,1526.64 h60
  text "ADDITIONAL REQUIREMENTS:" at 11332.46,1385.64 h60
  text "MICROSECTION:" at 11407.23,1270.64 h60
  text "YES" at 12312.96,1270.64 h60
  text "REQUIRED" at 13174.46,1114.49 h60
  text "BARE BOARD ELEC. TEST:" at 11407.23,1111.64 h60
  text "NONE" at 12712.96,1111.64 h60
  text "X" at 13047.46,1111.64 h60
  text "PER ORDER" at 13766.46,1111.64 h60
  text "MANUFACTURER'S UL:" at 11407.23,954.64 h60
  text "RAIL" at 12572.96,950.35 h60
  text "METAL" at 13064.77,950.35 h60
  text "X" at 13440,950 h60
  text "SILK" at 13576.46,950.35 h60
  text ".Layer_Name" at 577,-858.49 h60
M11 Gerber Information:
  lines w10: -292,-930.17 6308,-930.17 ; -292,-726.83 6310,-726.83 ; -292,-523.5 -292,-1133.5 3713,-1133.5 6310,-1133.5 6310,-523.5 -291.5,-523.5 -291.5,-1133.5 1284,-1133.5 ; 2173,-1133.5 2173,-523.5 ; 3440,-726.83 3440,-523.5 ; 4280,-726.83 4280,-523.5 ; 4902,-1140 4902,-937.17
  text "ALL ARTWORK VIEWED FROM TOP SIDE" at -228.5,-655.67 h60
  text "BOARD #:" at 2248,-655.67 h60
  text ".PRJ_Number" at 2793.5,-655.67 h60
  text "REV:" at 3638,-655.67 h60
  text ".PCB_Rev" at 3929.5,-655.67 h60
  text "SVN REV:" at 4476,-655.67 h60
  text ".VersionControl_RevNumber" at 4982,-655.67 h60
  text "LAYER NAME =" at -228.5,-858.49 h60
  text "TID #:" at 2248,-859 h60
  text ".TID" at 2793.5,-859 h60
  text "PLOT NAME =" at -228.5,-1064.34 h60
  text ".plot_File_Name" at 577,-1064.34 h60
  text "GENERATED    :" at 2250,-1064.34 h60
  text ".Print_Date" at 3119.5,-1064.34 h60
  text ".Print_Time" at 3848.5,-1064.34 h60
  text "TEXAS INSTRUMENTS" at 5113,-1064.34 h60
M12 Stackup:
  drawing of 191 lines, arcs and shapes, not listed
  text "Layer" at 9790.58,7830 h60
  text "Name" at 10200.49,7830 h60
  text "Material" at 11130.23,7830 h60
  text "Thickness" at 11990,7830 h60
  text "Constant" at 12639.84,7830 h60
  text "Board Layer Stack" at 13209.7,7830 h60
  text "1" at 9790.58,7710 h60
  text "Top Overlay" at 10200.49,7710 h60
  text "2" at 9790.58,7590 h60
  text "Top Solder" at 10200.49,7590 h60
  text "Solder Resist" at 11130.23,7590 h60
  text "0.40mil" at 11990,7590 h60
  text "3.5" at 12639.84,7590 h60
  text "3" at 9790.58,7470 h60
  text "Top Layer" at 10200.49,7470 h60
  text "Copper" at 11130.23,7470 h60
  text "1.40mil" at 11990,7470 h60
  text "4" at 9790.58,7350 h60
  text "Dielectric1" at 10200.49,7350 h60
  text "FR-4" at 11130.23,7350 h60
  text "59.20mil" at 11990,7350 h60
  text "4.8" at 12639.84,7350 h60
  text "5" at 9790.58,7230 h60
  text "Bottom Layer" at 10200.49,7230 h60
  text "Copper" at 11130.23,7230 h60
  text "1.40mil" at 11990,7230 h60
  text "6" at 9790.58,7110 h60
  text "Bottom Solder" at 10200.49,7110 h60
  text "Solder Resist" at 11130.23,7110 h60
  text "0.40mil" at 11990,7110 h60
  text "3.5" at 12639.84,7110 h60
  text "7" at 9790.58,6990 h60
  text "Bottom Overlay" at 10200.49,6990 h60
  text ".Layer_Name" at 577,-858.49 h60
M13 Component Bodies Top:
  text ".Layer_Name" at 577,-858.49 h60
M14 Component Bodies Bottom:
  text ".Layer_Name" at 577,-858.49 h60
M15 Courtyards Top:
  text ".Layer_Name" at 577,-858.49 h60
M16 Courtyards Bottom:
  text ".Layer_Name" at 577,-858.49 h60
Drill Drawing:
  lines w10: 5526.6,3082.92 5570.7,3082.92 5570.7,3127.01 5526.6,3127.01 5526.6,3082.92 ; 5526.6,3182.13 5548.65,3193.15 5570.7,3182.13 5559.68,3204.18 5570.7,3226.22 5548.65,3215.2 5526.6,3226.22 5537.63,3204.18 5526.6,3182.13 ; 5526.6,3292.36 5537.63,3292.36 5537.63,3281.34 5559.68,3281.34 5559.68,3292.36 5570.7,3292.36 5570.7,3314.41 5559.68,3314.41 5559.68,3325.43 5537.63,3325.43 5537.63,3314.41 5526.6,3314.41 5526.6,3292.36 ; 5535.42,3091.74 5561.88,3091.74 5561.88,3118.19 5535.42,3118.19 5535.42,3091.74
  lines w12: 5486,3053.16 7372.49,3053.16 ; 5486,3350.79 7372.49,3350.79 ; 5801.13,2953.94 5801.13,3450 ; 6117.88,2953.94 6117.88,3450 ; 6738.9,2953.94 6738.9,3450 ; 6982.83,2953.94 6982.83,3450 ; 5486,2953.94 7372.49,2953.94 7372.49,3450 5486,3450 5486,2953.94
  text "Symbol" at 5545.53,3380.55 h72
  text "Quantity" at 5830.9,3380.55 h72
  text "Finished Hole Size" at 6147.64,3380.55 h72
  text "Plated" at 6768.66,3380.55 h72
  text "Hole Type" at 7012.59,3380.55 h72
  text "15" at 5830.9,3281.34 h60
  text "28.00mil (0.711mm)" at 6147.64,3281.34 h60
  text "PTH" at 6768.66,3281.34 h60
  text "Round" at 7012.59,3281.34 h60
  text "7" at 5830.9,3182.13 h60
  text "98.43mil (2.500mm)" at 6147.64,3182.13 h60
  text "PTH" at 6768.66,3182.13 h60
  text "Round" at 7012.59,3182.13 h60
  text "3" at 5830.9,3082.92 h60
  text "214.57mil (5.450mm)" at 6147.64,3082.92 h60
  text "PTH" at 6768.66,3082.92 h60
  text "Round" at 7012.59,3082.92 h60
  text "25 Total" at 5830.9,2983.71 h60
  text ".Layer_Name" at 577,-858.49 h60

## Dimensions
0,0 to 0,5000 on M2 Board Dimensions
0,0 to 3580,5000 on M2 Board Dimensions
0,-400 to 1000,-400 on M2 Board Dimensions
